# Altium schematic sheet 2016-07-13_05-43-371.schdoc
size 322 x 134 mm; SheetNumber: 1; SheetTotal: 1
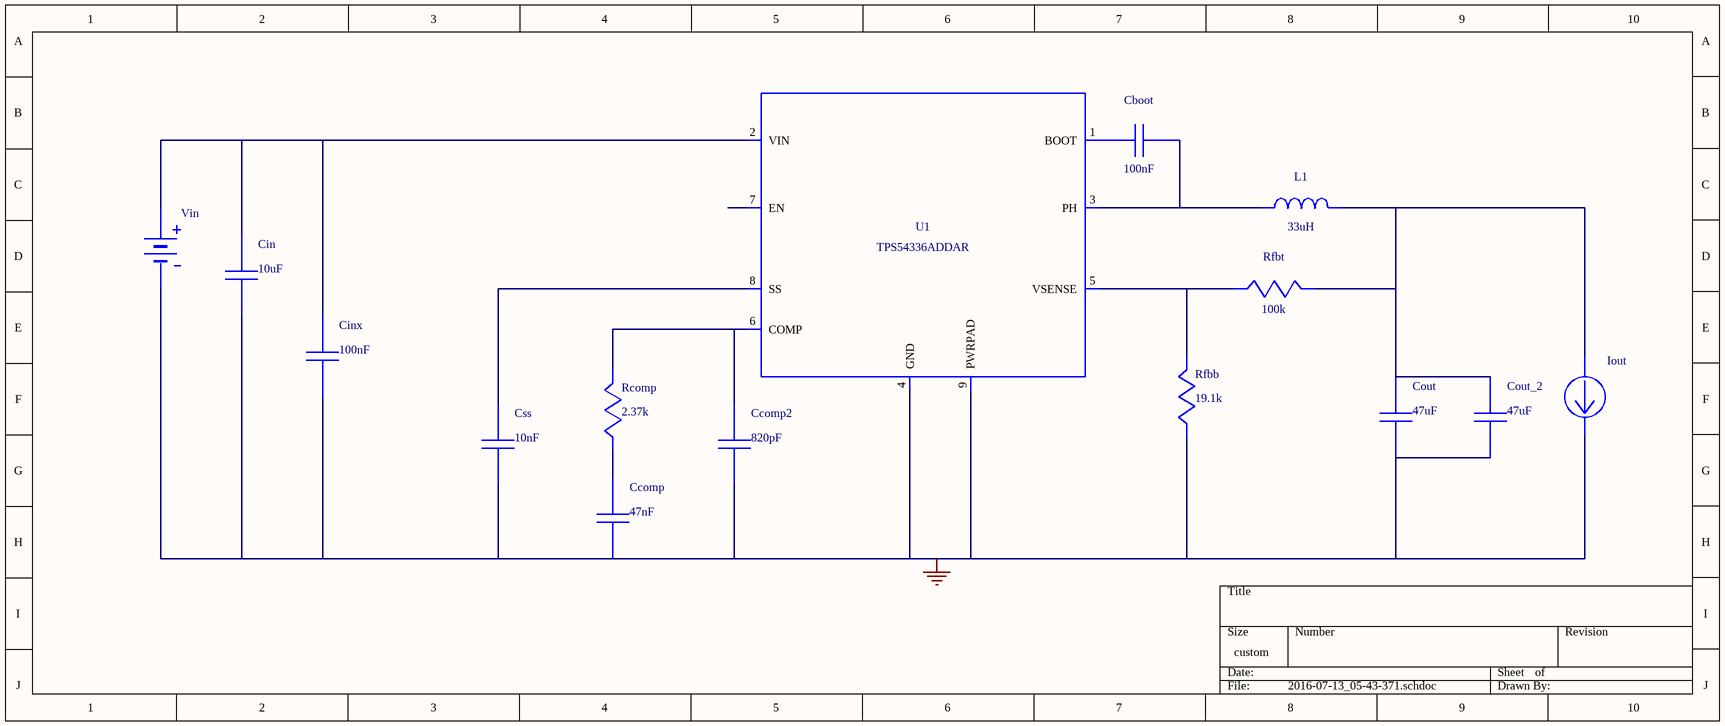
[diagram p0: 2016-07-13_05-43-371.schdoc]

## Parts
Cboot  value 100nF  (hidden comment: C0805C104K5RACTU)
Ccomp  value 47nF  (hidden comment: TMK212B7473KD-T)
Ccomp2  value 820pF  (hidden comment: CC0805KRX7R9BB821)
Cin  value 10uF  (hidden comment: GRM21BR61C106KE15L)
Cinx  value 100nF  (hidden comment: C0805C104K5RACTU)
Cout  value 47uF  (hidden comment: GRM31CR61A476KE15L)
Cout_2  value 47uF  (hidden comment: GRM31CR61A476KE15L)
Css  value 10nF  (hidden comment: GRM033R61A103KA01D)
Iout  WB_CURRENT_LOAD  (value not drawn)
L1  value 33uH  (hidden comment: SDR1105-330KL)
Rcomp  value 2.37k  (hidden comment: CRCW04022K37FKED)
Rfbb  value 19.1k  (hidden comment: CRCW040219K1FKED)
Rfbt  value 100k  (hidden comment: CRCW0402100KFKED)
U1  TPS54336DDAR  (value not drawn)
Vin  WB_BATTERY  (value not drawn)

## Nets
0: Ccomp.2 Ccomp2.2 Cin.2 Cinx.2 Cout.2 Cout_2.2 Css.2 Iout.2(-) Rfbb.2 U1.4(GND) U1.9(PWRPAD) Vin.2(-)
NetCboot_1: Cboot.1 U1.1(BOOT)
NetCboot_2: Cboot.2 L1.1 U1.3(PH)
NetCcomp2_1: Ccomp2.1 Rcomp.1 U1.6(COMP)
NetCcomp_1: Ccomp.1 Rcomp.2
NetCin_1: Cin.1 Cinx.1 U1.2(VIN) Vin.1(+)
NetCout_1: Cout.1 Cout_2.1 Iout.1(+) L1.2 Rfbt.1
NetCss_1: Css.1 U1.8(SS)
NetRfbb_1: Rfbb.1 Rfbt.2 U1.5(VSENSE)

Not connected (* = marked no-connect by the designer): U1 7(EN)

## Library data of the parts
Cboot Cinx = C0805C104K5RACTU: Manufacturer Name: Kemet
Ccomp = TMK212B7473KD-T: Manufacturer Name: Taiyo Yuden
Ccomp2 = CC0805KRX7R9BB821: CC0805KRX7R9BB82; Manufacturer Name: Yageo America
Cin = GRM21BR61C106KE15L: GRM21BR61C106KE1; Manufacturer Name: MuRata
Cout Cout_2 = GRM31CR61A476KE15L: GRM31CR61A476KE1; Manufacturer Name: MuRata
Css = GRM033R61A103KA01D: GRM033R61A103KA0; Manufacturer Name: MuRata
L1 = SDR1105-330KL: Manufacturer Name: Bourns
Rcomp = CRCW04022K37FKED: Manufacturer Name: Vishay-Dale
Rfbb = CRCW040219K1FKED: Manufacturer Name: Vishay-Dale
Rfbt = CRCW0402100KFKED: Manufacturer Name: Vishay-Dale
U1 = TPS54336DDAR: TPS54336ADDAR; Manufacturer Name: Texas Instruments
